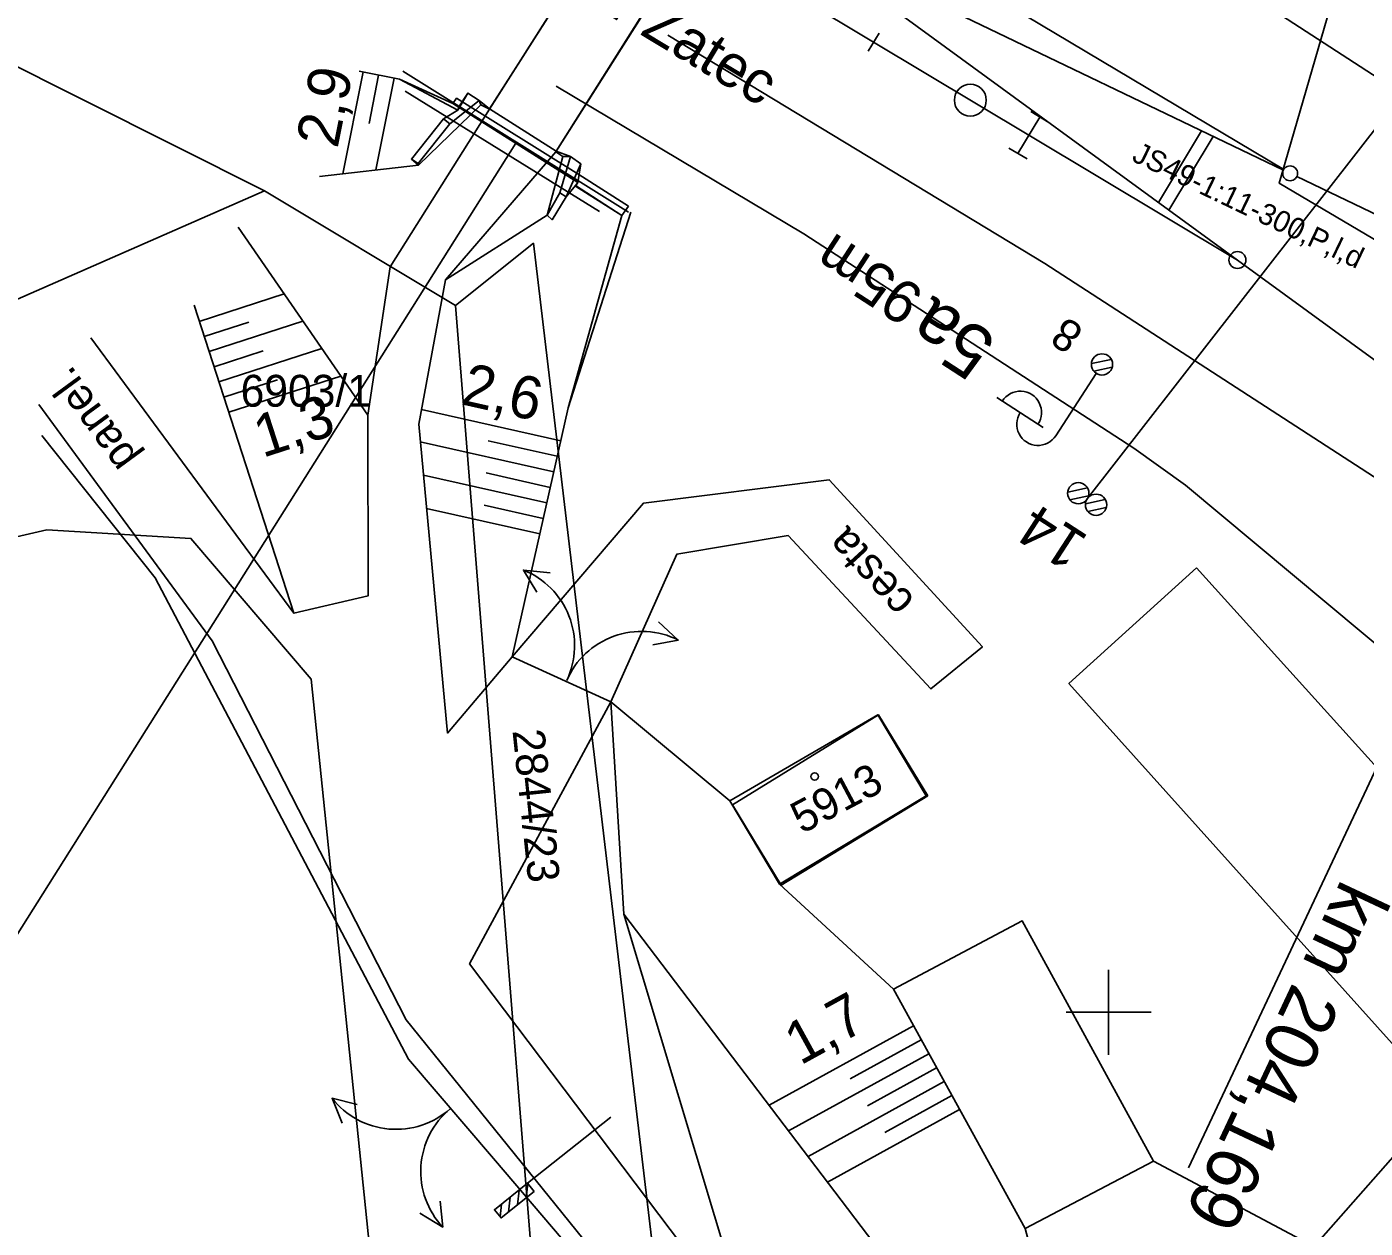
# Model space of a CAD drawing. Extents: x -800194 to -799078, y -1007177 to -1006597.
# Drawn here: x -799850.9 to -799787.9, y -1007010.2 to -1006953.6 of the extents above; entities that cross this region are included whole.
import ezdxf

# ---------------------------------------------------------------- set-up
doc = ezdxf.new("R2010")
doc.units = 0
for name, color, linetype in [('02_Osa_koleje', 7, 'Continuous'), ('_návrh', 7, 'Continuous'), ('_popvyt', 7, 'Continuous'), ('Ramove udaje', 7, 'Continuous'), ('Vrstva 1', 7, 'Continuous'), ('Vrstva 11', 7, 'Continuous'), ('Vrstva 17', 7, 'Continuous'), ('Vrstva 18', 7, 'Continuous'), ('Vrstva 2', 7, 'Continuous'), ('Vrstva 23', 7, 'Continuous'), ('Vrstva 25', 7, 'Continuous'), ('Vrstva 3', 7, 'Continuous'), ('Vrstva 4', 7, 'Continuous'), ('Vrstva 45', 7, 'Continuous'), ('Vrstva 48', 7, 'Continuous'), ('Vrstva 49', 7, 'Continuous'), ('Vrstva 5', 7, 'Continuous'), ('Vrstva 51', 7, 'Continuous'), ('Vrstva 53', 7, 'Continuous'), ('Vrstva 55', 7, 'Continuous'), ('Vrstva 57', 7, 'Continuous'), ('Vrstva 59', 7, 'Continuous'), ('Vrstva 7', 7, 'Continuous')]:
    doc.layers.add(name, color=color, linetype=linetype)

msp = doc.modelspace()

# ---------------------------------------------------------------- linework, layer by layer
at = {"layer": '_návrh'}
for p, q in [((-799820.103, -1006945.483), (-799793.935, -1006964.581)), ((-799791.756, -1006960.321), (-799808.622, -1006950.239)), ((-799791.771, -1006960.349), (-799809.481, -1006951.835)), ((-799791.14, -1006960.652), (-799779.191, -1006966.397))]:
    msp.add_line(p, q, dxfattribs=at)
for points in [[(-799821.595, -1006948.007), (-799811.064, -1006954.324), (-799803.753, -1006958.707), (-799793.935, -1006964.581), (-799784.224, -1006971.671), (-799782.913, -1006972.63), (-799767.418, -1006984.719), (-799752.333, -1006998.173), (-799735.027, -1007015.997), (-799721.623, -1007030.81), (-799713.555, -1007039.726), (-799713.111, -1007040.218)], [(-799820.755, -1006954.001), (-799803.004, -1006964.743), (-799786.682, -1006975.322), (-799769.882, -1006987.807), (-799754.745, -1007000.643), (-799736.311, -1007017.261), (-799721.623, -1007030.81)]]:
    msp.add_lwpolyline(points, dxfattribs=at)
msp.add_circle((-799791.455, -1006960.501), 0.35, dxfattribs=at)
at = {"layer": 'Ramove udaje'}
for p, q in [((-799800, -1006998), (-799800, -1007002)), ((-799802, -1007000), (-799800, -1007000)), ((-799800, -1007000), (-799798, -1007000))]:
    msp.add_line(p, q, dxfattribs=at)
at = {"layer": 'Vrstva 1'}
msp.add_lwpolyline([(-799773.482, -1006996.72), (-799784.684, -1006984.939), (-799796.383, -1006975.181), (-799798.809, -1006973.435), (-799814.345, -1006963.355), (-799826.008, -1006956.394)], dxfattribs=at)
at = {"layer": 'Vrstva 11'}
for p, q in [((-799801.01, -1006975.832), (-799786.978, -1006957.812)), ((-799801.001, -1006975.309), (-799801.925, -1006975.506)), ((-799800.947, -1006975.681), (-799801.822, -1006975.868)), ((-799800.16, -1006975.857), (-799801.087, -1006976.054)), ((-799800.108, -1006976.229), (-799800.981, -1006976.415))]:
    msp.add_line(p, q, dxfattribs=at)
for centre in [(-799801.429, -1006975.56), (-799800.591, -1006976.104)]:
    msp.add_circle(centre, 0.5, dxfattribs=at)
at = {"layer": 'Vrstva 17'}
for p, q in [((-799822.595, -1006962.333), (-799833.226, -1006955.692)), ((-799823.433, -1006985.376), (-799828.082, -1006983.271)), ((-799817.838, -1006990.049), (-799823.433, -1006985.376)), ((-799810.13, -1006998.908), (-799815.5, -1006993.967)), ((-799832.962, -1007002.208), (-799828.95, -1007006.881)), ((-799797.881, -1007007.005), (-799788.905, -1007011.78))]:
    msp.add_line(p, q, dxfattribs=at)
for points in [[(-799828.082, -1006983.271), (-799825.442, -1006971.542), (-799822.487, -1006962.331)], [(-799850.223, -1006972.842), (-799844.883, -1006979.549), (-799832.962, -1007002.208)], [(-799826.287, -1006979.308), (-799827.545, -1006979.177), (-799826.923, -1006980.227)], [(-799821.185, -1006981.617), (-799820.257, -1006982.477), (-799821.457, -1006982.702)], [(-799836.078, -1007005.216), (-799836.556, -1007004.045), (-799835.373, -1007004.348)], [(-799828.95, -1007006.881), (-799820.579, -1007016.712), (-799786.808, -1007048.821), (-799777.641, -1007052.247), (-799745.452, -1007060.292), (-799727.709, -1007066.187)], [(-799832.43, -1007009.465), (-799831.345, -1007010.115), (-799831.465, -1007008.9)]]:
    msp.add_lwpolyline(points, dxfattribs=at)
for centre, start, end in [((-799828.974, -1006982.735), 334.60495, 68.12483), ((-799821.989, -1006985.898), 63.15451, 156.67439), ((-799833.541, -1007001.676), 218.16255, 311.68243), ((-799828.546, -1007007.494), 129.61299, 223.13287)]:
    msp.add_arc(centre, 3.834, start, end, dxfattribs=at)
at = {"layer": 'Vrstva 18'}
for p, q in [((-799829.152, -1006957.479), (-799818.799, -1006941.218)), ((-799818.724, -1006941.148), (-799829.145, -1006957.469)), ((-799826.019, -1006959.481), (-799815.665, -1006943.128)), ((-799815.675, -1006943.054), (-799826.005, -1006959.461)), ((-799830.693, -1006956.963), (-799830.868, -1006957.21)), ((-799829.55, -1006957.279), (-799829.638, -1006957.076)), ((-799832.482, -1006960.109), (-799829.55, -1006957.279)), ((-799824.983, -1006960.928), (-799830.59, -1006957.375)), ((-799831.313, -1006957.935), (-799831.008, -1006958.165)), ((-799827.908, -1006959.087), (-799870.441, -1007026.562)), ((-799825.693, -1006959.713), (-799825.325, -1006959.713)), ((-799824.992, -1006960.93), (-799824.839, -1006960.052)), ((-799825.834, -1006961.412), (-799825.53, -1006961.608)), ((-799825.101, -1006961.073), (-799825.103, -1006961.108))]:
    msp.add_line(p, q, dxfattribs=at)
for points in [[(-799830.868, -1006957.21), (-799833.381, -1006956.07), (-799830.63, -1006957.53)], [(-799830.63, -1006957.53), (-799831.313, -1006957.935), (-799832.822, -1006959.833), (-799832.509, -1006960.04), (-799831.008, -1006958.165), (-799829.638, -1006957.076)], [(-799822.606, -1006962.05), (-799822.921, -1006962.486), (-799825.103, -1006961.108), (-799824.983, -1006960.928), (-799830.878, -1006957.218), (-799830.693, -1006956.963), (-799824.939, -1006960.553), (-799822.606, -1006962.05)], [(-799830.63, -1006957.53), (-799830.59, -1006957.375), (-799830.868, -1006957.21), (-799830.878, -1006957.218)], [(-799824.839, -1006960.052), (-799825.325, -1006959.713), (-799826.005, -1006959.461), (-799829.145, -1006957.469), (-799829.638, -1006957.076), (-799830.162, -1006956.72), (-799830.63, -1006957.53)], [(-799830.59, -1006957.375), (-799830.162, -1006956.72)], [(-799829.55, -1006957.279), (-799829.152, -1006957.479), (-799829.145, -1006957.469)], [(-799826.428, -1006962.473), (-799825.693, -1006959.713), (-799826.019, -1006959.481), (-799826.005, -1006959.461)], [(-799824.839, -1006960.052), (-799825.53, -1006961.608), (-799826.201, -1006962.682), (-799826.428, -1006962.473), (-799825.834, -1006961.412), (-799825.325, -1006959.713)], [(-799832.822, -1006959.833), (-799832.482, -1006960.109), (-799832.509, -1006960.04)], [(-799824.983, -1006960.928), (-799824.839, -1006960.052)], [(-799822.921, -1006962.486), (-799825.101, -1006961.073), (-799824.992, -1006960.93)], [(-799824.992, -1006960.93), (-799824.983, -1006960.928), (-799824.983, -1006960.928)]]:
    msp.add_lwpolyline(points, dxfattribs=at)
at = {"layer": 'Vrstva 2'}
msp.add_line((-799810.807, -1006953.895), (-799811.321, -1006954.753), dxfattribs=at)
msp.add_circle((-799793.935, -1006964.581), 0.4, dxfattribs=at)
at = {"layer": 'Vrstva 23'}
for points in [[(-799795.856, -1006979.079), (-799779.728, -1006996.929), (-799785.824, -1007002.398), (-799801.87, -1006984.513), (-799795.856, -1006979.079)], [(-799815.5, -1006993.967), (-799817.838, -1006990.049), (-799810.865, -1006985.994), (-799808.586, -1006989.81), (-799815.5, -1006993.967)], [(-799797.881, -1007007.005), (-799803.933, -1007010.185), (-799810.13, -1006998.908), (-799804.077, -1006995.693), (-799797.881, -1007007.005)]]:
    msp.add_lwpolyline(points, dxfattribs=at)
at = {"layer": 'Vrstva 25'}
for p, q in [((-799799.875, -1006969.26), (-799800.811, -1006969.46)), ((-799799.832, -1006969.634), (-799800.693, -1006969.818)), ((-799800.585, -1006969.917), (-799802.489, -1006972.854)), ((-799803.076, -1006972.473), (-799805.258, -1006971.059))]:
    msp.add_line(p, q, dxfattribs=at)
msp.add_circle((-799800.313, -1006969.497), 0.5, dxfattribs=at)
for centre, start, end in [((-799804.16, -1006971.756), 326.34839, 147.75354), ((-799803.328, -1006972.31), 147.05097, 327.05097)]:
    msp.add_arc(centre, 1, start, end, dxfattribs=at)
at = {"layer": 'Vrstva 3'}
for p, q in [((-799803.668, -1006957.592), (-799802.81, -1006958.106)), ((-799803.239, -1006957.849), (-799804.267, -1006959.565)), ((-799804.696, -1006959.308), (-799803.838, -1006959.822)), ((-799769.882, -1006987.807), (-799828.64, -1007054.5))]:
    msp.add_line(p, q, dxfattribs=at)
at = {"layer": 'Vrstva 4'}
for p, q in [((-799796.383, -1006975.181), (-799798.809, -1006973.435)), ((-799823.436, -1007004.934), (-799827.348, -1007008.048)), ((-799827.339, -1007008.059), (-799827.417, -1007008.742)), ((-799828.167, -1007008.7), (-799828.247, -1007009.403)), ((-799827.752, -1007008.369), (-799827.832, -1007009.072)), ((-799828.582, -1007009.03), (-799828.649, -1007009.624))]:
    msp.add_line(p, q, dxfattribs=at)
msp.add_lwpolyline([(-799827.037, -1007008.439), (-799828.601, -1007009.685), (-799828.913, -1007009.293), (-799827.348, -1007008.048)], close=True, dxfattribs=at)
at = {"layer": 'Vrstva 45'}
msp.add_line((-799823.971, -1006962.296), (-799833.117, -1006956.632), dxfattribs=at)
at = {"layer": 'Vrstva 48'}
for p, q in [((-799835.097, -1006955.728), (-799836.053, -1006960.521)), ((-799834.362, -1006955.874), (-799834.816, -1006958.153)), ((-799833.626, -1006956.021), (-799834.488, -1006960.34)), ((-799842.804, -1006967.469), (-799838.815, -1006966.177)), ((-799842.573, -1006968.182), (-799840.472, -1006967.502)), ((-799842.342, -1006968.896), (-799837.926, -1006967.466)), ((-799842.111, -1006969.609), (-799839.796, -1006968.86)), ((-799841.88, -1006970.323), (-799837.036, -1006968.755)), ((-799841.649, -1006971.036), (-799839.12, -1006970.218)), ((-799841.417, -1006971.75), (-799836.147, -1006970.043)), ((-799825.79, -1006973.09), (-799832.349, -1006971.614)), ((-799826.12, -1006974.553), (-799832.401, -1006973.14)), ((-799825.955, -1006973.822), (-799829.214, -1006973.088)), ((-799826.449, -1006976.017), (-799832.255, -1006974.71)), ((-799826.284, -1006975.285), (-799829.306, -1006974.605)), ((-799826.779, -1006977.48), (-799832.109, -1006976.28)), ((-799826.614, -1006976.748), (-799829.398, -1006976.122)), ((-799809.18, -1007000.637), (-799815.985, -1007004.377)), ((-799808.819, -1007001.295), (-799812.172, -1007003.137)), ((-799808.457, -1007001.952), (-799815.067, -1007005.584)), ((-799808.096, -1007002.609), (-799811.352, -1007004.398)), ((-799807.735, -1007003.266), (-799814.149, -1007006.791)), ((-799807.374, -1007003.924), (-799810.532, -1007005.659)), ((-799807.013, -1007004.581), (-799813.231, -1007007.998))]:
    msp.add_line(p, q, dxfattribs=at)
at = {"layer": 'Vrstva 49'}
for points in [[(-799809.896, -1006941.363), (-799780.709, -1006960.303)], [(-799830.63, -1006957.53), (-799833.381, -1006956.07), (-799835.276, -1006955.692)], [(-799830.63, -1006957.53), (-799831.313, -1006957.935), (-799832.822, -1006959.833), (-799832.482, -1006960.109), (-799837.146, -1006960.647)], [(-799831.126, -1006986.858), (-799832.478, -1006972.309), (-799831.215, -1006965.513), (-799826.428, -1006962.473), (-799826.201, -1006962.682), (-799825.53, -1006961.608), (-799825.101, -1006961.073), (-799822.921, -1006962.486)], [(-799822.921, -1006962.486), (-799825.442, -1006971.542), (-799828.082, -1006983.271), (-799831.126, -1006986.858)], [(-799834.851, -1006980.391), (-799834.878, -1006971.883), (-799840.982, -1006963.036)], [(-799843.049, -1006966.712), (-799838.352, -1006981.216), (-799834.851, -1006980.391)], [(-799823.433, -1006985.376), (-799817.838, -1006990.049), (-799815.5, -1006993.967), (-799810.13, -1006998.908), (-799803.933, -1007010.185), (-799801.55, -1007019.072), (-799804.246, -1007020.27), (-799789.014, -1007035.746), (-799784.101, -1007040.767), (-799778.537, -1007044.165), (-799742.314, -1007053.114), (-799725.901, -1007057.997)], [(-799823.433, -1006985.376), (-799822.824, -1006995.382), (-799809.853, -1007012.441), (-799805.067, -1007021.457), (-799784.005, -1007043.381), (-799779.029, -1007045.556), (-799742.637, -1007054.554), (-799725.892, -1007059.592)], [(-799822.824, -1006995.382), (-799817.689, -1007012.452), (-799816.629, -1007013.288), (-799784.593, -1007044.315), (-799779.066, -1007046.684), (-799743.002, -1007056.174), (-799726.202, -1007060.605)]]:
    msp.add_lwpolyline(points, dxfattribs=at)
at = {"layer": 'Vrstva 5'}
msp.add_line((-799796.24, -1007007.322), (-799778.659, -1006969.886), dxfattribs=at)
at = {"layer": 'Vrstva 51'}
for points in [[(-799817.051, -1006918.973), (-799812.091, -1006931.542), (-799815.665, -1006943.128), (-799826.019, -1006959.481), (-799831.215, -1006965.513), (-799832.478, -1006972.309), (-799831.126, -1006986.858), (-799828.082, -1006983.271), (-799821.896, -1006976.034), (-799813.152, -1006974.923), (-799805.94, -1006982.791), (-799808.362, -1006984.771), (-799815.088, -1006977.554), (-799820.319, -1006978.428), (-799823.433, -1006985.376), (-799830.084, -1006997.726), (-799819.519, -1007011.695), (-799817.354, -1007013.08), (-799784.788, -1007044.956), (-799778.171, -1007047.694), (-799743.858, -1007056.783), (-799726.629, -1007061.89)], [(-799819.72, -1006920.416), (-799816.225, -1006931.712), (-799818.799, -1006941.218), (-799829.152, -1006957.479), (-799833.813, -1006964.907), (-799834.878, -1006971.883), (-799834.851, -1006980.391), (-799838.352, -1006981.216)], [(-799838.352, -1006981.216), (-799847.912, -1006968.244)], [(-799850.363, -1006971.39), (-799842.202, -1006982.511)], [(-799842.202, -1006982.511), (-799833.072, -1007000.361), (-799821.843, -1007014.249), (-799786.621, -1007048.212), (-799778.768, -1007050.961), (-799745.381, -1007058.848), (-799727.01, -1007064.42)]]:
    msp.add_lwpolyline(points, dxfattribs=at)
at = {"layer": 'Vrstva 53'}
msp.add_lwpolyline([(-799673.33, -1007118.14), (-799714.71, -1007110.97), (-799718.21, -1007083.69), (-799729.93, -1007087.54), (-799766.47, -1007095.84), (-799767.73, -1007094.8), (-799769.22, -1007093.56), (-799785.06, -1007080.42), (-799809.11, -1007056.81), (-799818.59, -1007034.4), (-799822.79, -1007029.13), (-799826.14, -1007024.13), (-799830.75, -1006966.73), (-799839.73, -1006961.33), (-799877.87, -1006942.17), (-799936.47, -1006903.99), (-799954.76, -1006895.45), (-799964.79, -1006890.84)], dxfattribs=at)
at = {"layer": 'Vrstva 55'}
for p, q in [((-799830.75, -1006966.73), (-799839.73, -1006961.33)), ((-799826.14, -1007024.13), (-799830.75, -1006966.73))]:
    msp.add_line(p, q, dxfattribs=at)
for points in [[(-799839.73, -1006961.33), (-799877.87, -1006942.17), (-799936.47, -1006903.99), (-799954.76, -1006895.45), (-799964.79, -1006890.84)], [(-799785.23, -1006937.71), (-799791.69, -1006959.99), (-799791.97, -1006960.97), (-799746.76, -1006987.67), (-799745.68, -1006988.03), (-799733.28, -1006992.13)], [(-799882.85, -1006975.35), (-799867.48, -1006973.49), (-799839.73, -1006961.33)], [(-799811.13, -1007032.26), (-799820.31, -1007020.81), (-799827.08, -1006963.79), (-799830.75, -1006966.73)], [(-799831.14, -1007046.62), (-799837.54, -1006984.31), (-799843.2, -1006977.69), (-799849.98, -1006977.29), (-799866.6, -1006981.12)], [(-799808.51, -1006989.81), (-799810.83, -1006986), (-799817.7, -1006990.24), (-799815.41, -1006994.01), (-799808.51, -1006989.81)]]:
    msp.add_lwpolyline(points, dxfattribs=at)
at = {"layer": 'Vrstva 59'}
msp.add_circle((-799813.837, -1006988.899), 0.175, dxfattribs=at)
at = {"layer": 'Vrstva 7'}
for p, q in [((-799795.627, -1006958.5), (-799797.645, -1006961.872)), ((-799795.084, -1006958.761), (-799797.158, -1006962.228)), ((-799796.379, -1006960.341), (-799796.379, -1006960.341))]:
    msp.add_line(p, q, dxfattribs=at)
msp.add_circle((-799806.51, -1006957.054), 0.75, dxfattribs=at)

# ---------------------------------------------------------------- texts
at = {"layer": '02_Osa_koleje'}
msp.add_text('TÚ 0101 - směr Žatec', height=2, rotation=328.93903, dxfattribs=at).set_placement((-799838.658, -1006943.961))
at = {"layer": '_popvyt'}
msp.add_text('      JS49-1:11-300,P,l,d', height=1, rotation=334.32513, dxfattribs=at).set_placement((-799800.968, -1006958.927))
at = {"layer": 'Vrstva 1'}
for s, height, p in [('95m', 2, (-799808.58, -1006966.081)), ('5a', 2.5, (-799805.164, -1006968.263))]:
    msp.add_text(s, height=height, rotation=147.02386, dxfattribs=at).set_placement(p)
at = {"layer": 'Vrstva 11'}
msp.add_text('14', height=2, rotation=147.02386, dxfattribs=at).set_placement((-799800.876, -1006977.628))
at = {"layer": 'Vrstva 25'}
msp.add_text('8', height=1.5, rotation=147.05097, dxfattribs=at).set_placement((-799801.102, -1006967.811))
at = {"layer": 'Vrstva 48'}
for s, rotation, p in [('2,9', 78.71914, (-799836.302, -1006959.367)), ('2,6', 347.31508, (-799830.553, -1006971.357)), ('1,3', 17.94412, (-799839.826, -1006973.903)), ('1,7', 28.78992, (-799814.513, -1007002.518))]:
    msp.add_text(s, height=2, rotation=rotation, dxfattribs=at).set_placement(p)
at = {"layer": 'Vrstva 5'}
msp.add_text('km 204,169', height=2.5, rotation=244.84361, dxfattribs=at).set_placement((-799789.022, -1006993.664))
at = {"layer": 'Vrstva 51'}
for s, rotation, p in [('panel.', 126.27259, (-799845.639, -1006973.877)), ('cesta', 132.50913, (-799809.061, -1006980.573))]:
    msp.add_text(s, height=1.5, rotation=rotation, dxfattribs=at).set_placement(p)
at = {"layer": 'Vrstva 57'}
msp.add_text('6903/1', height=1.5, dxfattribs=at).set_placement((-799840.861, -1006971.488))
for s, rotation, p in [('2844/23', 276, (-799828.065, -1006986.738)), ('5913', 28, (-799814.44, -1006991.622))]:
    msp.add_text(s, height=1.5, rotation=rotation, dxfattribs=at).set_placement(p)

doc.saveas('drawing.dxf')
